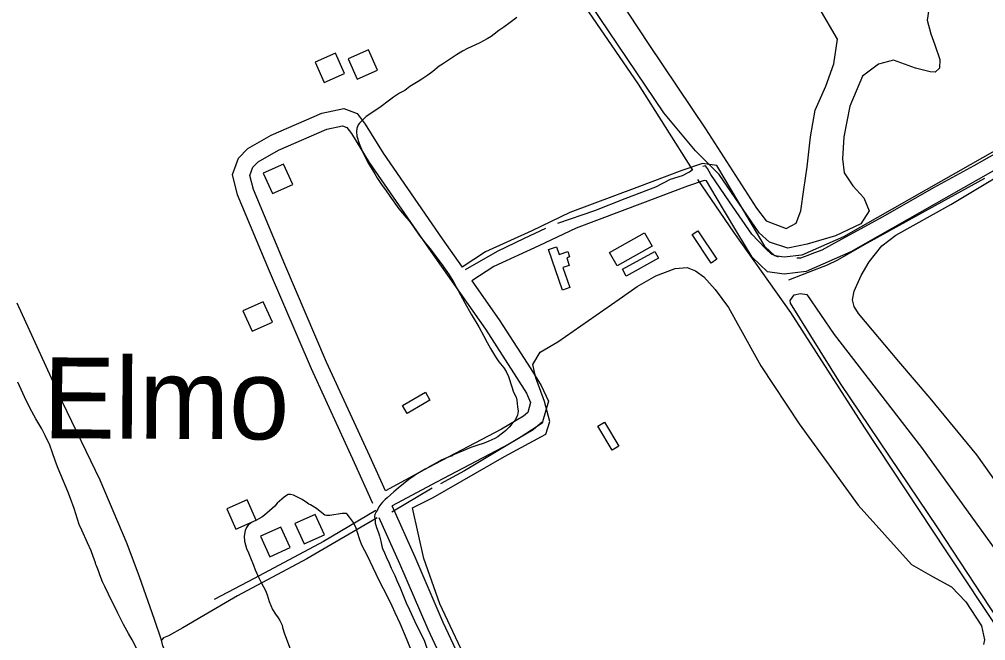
# Model space of a CAD drawing. Extents: x 3392644 to 3430565, y 576657 to 602123.
# Drawn here: x 3398161 to 3399896, y 589018 to 590133 of the extents above; entities that cross this region are included whole.
import ezdxf

# ---------------------------------------------------------------- set-up
doc = ezdxf.new("R2010")
doc.units = 0
for name, color, linetype in [('V-BLDG-OTLN', 7, 'Continuous'), ('V-ROAD-CNTR', 7, 'Continuous'), ('V-SITE-VEGE', 7, 'Continuous'), ('V-TOPO-GNAM-IDEN', 7, 'Continuous'), ('V-TOPO-SHOR', 7, 'Continuous')]:
    doc.layers.add(name, color=color, linetype=linetype)

msp = doc.modelspace()

# ---------------------------------------------------------------- linework, layer by layer
at = {"layer": 'V-BLDG-OTLN'}
for points in [[(3398804.1, 590042.1), (3398787.7, 590078.6), (3398751.2, 590062.2), (3398767.6, 590025.7)], [(3398744.7, 590036.3), (3398728.3, 590072.8), (3398691.8, 590056.4), (3398708.2, 590019.9)], [(3398651.8, 589836.9), (3398635.4, 589873.4), (3398598.9, 589857), (3398615.3, 589820.5)], [(3399296.8, 589726.1), (3399233.9, 589690.7), (3399220.4, 589714.7), (3399283.3, 589750.1)], [(3399402.7, 589695.8), (3399368.9, 589747.2), (3399379.2, 589754), (3399413, 589702.6)], [(3399136.2, 589647.5), (3399111, 589720.4), (3399125, 589725.2), (3399129.9, 589711), (3399145.5, 589716.4), (3399148.8, 589706.9), (3399143.5, 589705.1), (3399148.1, 589691.8), (3399136.6, 589687.9), (3399149, 589651.9)], [(3399308.6, 589704.6), (3399250.4, 589672.4), (3399243.6, 589684.7), (3399301.8, 589716.9)], [(3398615.2, 589590), (3398598.8, 589626.5), (3398562.3, 589610.2), (3398578.7, 589573.7)], [(3398848.9, 589440.2), (3398889.9, 589464.2), (3398898.1, 589450), (3398857.2, 589426.1)], [(3399211.3, 589410.4), (3399237.1, 589367.5), (3399225.1, 589360.3), (3399199.3, 589403.1)], [(3398586.3, 589234.8), (3398569.9, 589271.3), (3398533.4, 589254.9), (3398549.8, 589218.5)], [(3398708.7, 589208.2), (3398692.3, 589244.7), (3398655.8, 589228.4), (3398672.2, 589191.9)], [(3398647, 589185.5), (3398630.7, 589221.9), (3398594.2, 589205.6), (3398610.6, 589169.1)]]:
    msp.add_lwpolyline(points, close=True, dxfattribs=at)
at = {"layer": 'V-ROAD-CNTR'}
for points in [[(3400711.5, 590349.2), (3400649.5, 590311.2), (3400302.5, 590119), (3399788.6, 589827.2), (3399640.3, 589742.8), (3399565.5, 589710.1), (3399533.9, 589706.2), (3399517.4, 589708.6), (3399500, 589725.1), (3399476.5, 589764.4), (3399450.7, 589807.6), (3399427.9, 589845.8), (3399413, 589870.9), (3399387.4, 589874.5), (3399350.1, 589862), (3399269.3, 589831.7), (3399149, 589786.4), (3399080.9, 589753.9), (3398998.1, 589716.1), (3398955.9, 589688.4)], [(3400727.1, 590323.6), (3400664.6, 590285.3), (3400317.1, 590092.8), (3399803.4, 589801.1), (3399653.7, 589716), (3399573.5, 589680.9), (3399533.6, 589675.9), (3399503.7, 589680.3), (3399476.3, 589706.2), (3399450.8, 589749), (3399425, 589792.2), (3399402.2, 589830.4), (3399394.5, 589843.2), (3399390.2, 589843.8), (3399360.2, 589833.7), (3399279.8, 589803.6), (3399160.8, 589758.8), (3399093.6, 589726.8), (3399012.7, 589689.7), (3398973.2, 589663.8)], [(3398795.4, 589264.8), (3398762.8, 589337.3), (3398685.2, 589506), (3398610.1, 589681.6), (3398552.6, 589818.5), (3398543.4, 589854.7), (3398554.3, 589884.1), (3398571, 589901.6), (3398612.9, 589925.2), (3398704.1, 589965), (3398743.6, 589973), (3398767.6, 589964.1), (3398781.8, 589945.2), (3398814.3, 589893), (3398919.8, 589739.6), (3398955.9, 589688.4)], [(3398818.1, 589287.5), (3398790.1, 589349.7), (3398712.6, 589518.2), (3398637.7, 589693.3), (3398581.1, 589828.1), (3398574.8, 589853), (3398580.3, 589867.9), (3398589.6, 589877.7), (3398626.3, 589898.3), (3398713.2, 589936.3), (3398741.2, 589941.9), (3398748.9, 589939.1), (3398757, 589928.3), (3398789.2, 589876.5), (3398895.2, 589722.5), (3398997.6, 589577.1), (3399053.6, 589490.3), (3399071.1, 589462.2), (3399078.8, 589445.7), (3399073.6, 589427.8), (3399066, 589421.1), (3399026.5, 589397.9), (3398895.6, 589329.2), (3398818.1, 589287.5)], [(3398973.2, 589663.8), (3399022.5, 589593.9), (3399079, 589506.3), (3399097.5, 589476.5), (3399110.7, 589448.1), (3399099.9, 589410.9), (3399083.6, 589396.7), (3399041.1, 589371.7), (3398909.7, 589302.7), (3398830.4, 589260.1)], [(3399121.8, 588567.7), (3399100.4, 588614.9), (3399064.5, 588719.1), (3399033.2, 588806), (3398982, 588922.5), (3398922.1, 589050.7), (3398871.7, 589168.3), (3398830.4, 589260.1)], [(3398801.1, 589252.2), (3398706.9, 589196.6), (3398582.7, 589129.8), (3398510.7, 589092.2)], [(3399095.7, 588552.4), (3399072.5, 588603.8), (3399036.2, 588709.1), (3399005.4, 588794.9), (3398954.7, 588910.1), (3398894.7, 589038.4), (3398844.2, 589156.2), (3398807.2, 589238.6)]]:
    msp.add_lwpolyline(points, dxfattribs=at)
at = {"layer": 'V-SITE-VEGE'}
for points in [[(3399178.7, 590259.3), (3399291.1, 590088.2), (3399392.7, 589937), (3399484.2, 589794.6), (3399501.3, 589771.5), (3399537.4, 589757.7), (3399555.7, 589767.7), (3399563.8, 589789.7), (3399569, 589827.6), (3399575, 589868.5), (3399581.2, 589922.1), (3399589.7, 589970.2), (3399608.4, 590013.4), (3399623, 590053.5), (3399629.9, 590097.6), (3399596.6, 590154)], [(3399793.5, 590151.7), (3399790.6, 590132), (3399797, 590107), (3399804.6, 590087.2), (3399813, 590061), (3399812.4, 590045.3), (3399804.8, 590038.6), (3399796.1, 590038.8), (3399769.4, 590045.4), (3399730.1, 590060.1), (3399703.2, 590052.5), (3399674.5, 590031.5), (3399651.7, 589977.3), (3399640.8, 589922.2), (3399638.8, 589882.8), (3399641.6, 589857.5), (3399657.1, 589834.4), (3399676.6, 589812.8), (3399686.6, 589789.8), (3399671.3, 589766.3), (3399626, 589744.8), (3399575.3, 589729.6), (3399540.5, 589722.9), (3399507.5, 589733.6), (3399488.8, 589750.4), (3399417.4, 589854.6), (3399374.5, 589897), (3399317.7, 589965.6), (3399170.3, 590185.2)], [(3399046.8, 590131.2), (3399042.2, 590127.5), (3399030.8, 590119.2), (3399021.8, 590112.9), (3399013.6, 590106.6), (3399007.7, 590102.4), (3399000.9, 590098.5), (3398987.6, 590091.2), (3398978.5, 590086.8), (3398965.2, 590080.7), (3398956.5, 590076), (3398945.7, 590069.3), (3398938.6, 590064.9), (3398920.6, 590052.9), (3398914.7, 590049.2), (3398903.2, 590039.6), (3398894.5, 590033.1), (3398883.3, 590025.7), (3398877.2, 590021.7), (3398867.9, 590016.5), (3398861.8, 590012.5), (3398853, 590005.4), (3398850.6, 590004.5), (3398843.7, 590000.7), (3398832.7, 589993.5), (3398825.5, 589988.3), (3398808.3, 589974.8), (3398783.8, 589958.9), (3398779.6, 589954.7), (3398776.7, 589951.7), (3398771.6, 589947.2), (3398769.5, 589943.7), (3398766.9, 589937.5), (3398766.1, 589931.7), (3398766.7, 589923.6), (3398770.9, 589910.3), (3398776.7, 589897.2), (3398786.6, 589876.2), (3398799.3, 589855.9), (3398803.9, 589847.5), (3398812.2, 589835.1), (3398818.1, 589827), (3398826.1, 589815.7), (3398842.5, 589793.5), (3398855.3, 589777.8), (3398860.5, 589771.7), (3398868.3, 589761.1), (3398879, 589746), (3398889.5, 589732.3), (3398898, 589722), (3398911, 589704.9), (3398919.9, 589692.9), (3398932.6, 589674.6), (3398941.1, 589660.8), (3398952.8, 589638.9), (3398960.7, 589624.3), (3398972.1, 589604), (3398986.1, 589581.2), (3398995.1, 589564.5), (3399000.6, 589553.5), (3399006.5, 589542.9), (3399015.7, 589527.5), (3399022, 589518.9), (3399030.5, 589507.9), (3399034.9, 589501.2), (3399038.8, 589492.5), (3399040.8, 589487.2), (3399043.1, 589479.2), (3399044.9, 589473.6), (3399047.6, 589466.2), (3399049.4, 589461.8), (3399052.9, 589455.2), (3399054, 589450.1), (3399055.5, 589438), (3399056.2, 589429.9), (3399055.5, 589422.7), (3399051.6, 589415.3), (3399049.5, 589411.9), (3399043.6, 589405.6), (3399040.3, 589401.5), (3399034.2, 589395.5), (3399030.6, 589392.2), (3399023.5, 589387.2), (3399019.9, 589384.4), (3399014.4, 589381.3), (3399004, 589376.2), (3398995.3, 589372.9), (3398982.4, 589368.4), (3398975.2, 589366.2), (3398968.6, 589363.7), (3398957.8, 589359.1), (3398948.5, 589355.5), (3398935.4, 589350), (3398939, 589350.9), (3398929.3, 589347.1), (3398918.5, 589342.5), (3398902.6, 589333.5), (3398895.6, 589329.3), (3398889.7, 589326.3), (3398875.4, 589317.9), (3398869.7, 589314.2)], [(3399053.8, 590136.4), (3399046.8, 590131.2)], [(3399948.2, 589254.9), (3399879.9, 589351.6), (3399795.9, 589453.3), (3399739.4, 589519.1), (3399667, 589605.2), (3399659.3, 589617.9), (3399656.7, 589629.8), (3399659.6, 589645.2), (3399672.2, 589673.8), (3399686.3, 589698.1), (3399709.1, 589726.7), (3399734.2, 589745.7), (3399833.2, 589801), (3399978.7, 589888)], [(3399014.5, 588874.6), (3398916, 589084.2), (3398887, 589165.8), (3398866.8, 589256.9), (3398904.1, 589275.4), (3399032.1, 589348.8), (3399106, 589389), (3399113.3, 589411.8), (3399103.5, 589447.4), (3399088.2, 589490.2), (3399083, 589514), (3399095.9, 589535.9), (3399127.7, 589554.5), (3399237.5, 589631.3), (3399270.2, 589653.8), (3399303.6, 589673.1), (3399338.4, 589686.1), (3399359.8, 589688.2), (3399374.7, 589681.8), (3399389.6, 589671.3), (3399409.8, 589648.2), (3399433.9, 589616.3), (3399452.5, 589582.9), (3399491.8, 589511.4), (3399560.9, 589407.2), (3399666.5, 589261.5), (3399762.3, 589155.3), (3399799.9, 589133.6), (3399834.4, 589115), (3399860.1, 589087.8), (3399888, 589044.9), (3399893.3, 589019.6), (3399891.6, 589011.7)], [(3399931.8, 589006.1), (3399935.9, 589020.2), (3399929.8, 589037.7), (3399809.6, 589220.7), (3399635.1, 589480.1), (3399545.3, 589624.1), (3399544.6, 589628.8), (3399551.8, 589639), (3399562.9, 589641.2), (3399574.7, 589639.5), (3399623.6, 589567.9), (3399780.6, 589364.7), (3400002.6, 589057.3), (3400213, 588764.3)], [(3398372.9, 589001.6), (3398363.7, 589019.7), (3398356.9, 589031.4), (3398347.9, 589047.4), (3398342.8, 589058), (3398337.8, 589067.7), (3398332.9, 589078.1), (3398325.6, 589092.7), (3398321.2, 589102), (3398314.4, 589115.3), (3398310.4, 589124), (3398305.3, 589136.3), (3398302.9, 589143.5), (3398299.3, 589152.6), (3398298.4, 589155.1), (3398297.5, 589158.1), (3398293.7, 589169.5), (3398290, 589179.5), (3398283.3, 589193.9), (3398273.4, 589216.7), (3398268.7, 589226.7), (3398259.5, 589255.5), (3398253.1, 589273.5), (3398248.4, 589286), (3398235.6, 589315.7), (3398230.9, 589327.3), (3398226.2, 589339.6), (3398220.2, 589357.4), (3398215.8, 589369.1), (3398207.6, 589386.6), (3398201.4, 589398.7), (3398190.9, 589416.6), (3398183.7, 589429.7), (3398173.6, 589449.2), (3398167.2, 589462.3), (3398158.1, 589482.4)], [(3398869.7, 589314.2), (3398860, 589307.5), (3398840.8, 589292), (3398833.5, 589285.7), (3398821.5, 589274.7), (3398817.9, 589271.6), (3398812.9, 589266.9), (3398809.9, 589263.6), (3398806.6, 589258.4), (3398804.3, 589254.1), (3398801.6, 589249.6), (3398799.2, 589244.5), (3398798.6, 589241), (3398798.9, 589237.2), (3398799.5, 589234.5), (3398800, 589229.3), (3398801, 589225.7), (3398802.1, 589221.3), (3398805.4, 589213.4), (3398807.4, 589206.7), (3398810.1, 589196.9), (3398811.8, 589187.8), (3398813.1, 589183.9), (3398816.7, 589175.9), (3398819.3, 589169.1), (3398824.6, 589157.5), (3398828.4, 589148.6), (3398834.8, 589135.1), (3398838.5, 589126.4), (3398844.7, 589113.3), (3398855.6, 589086.4), (3398861.1, 589073.7), (3398870.2, 589054), (3398877.2, 589040), (3398887.6, 589019.1), (3398892.5, 589005.1)], [(3398863.3, 589004.6), (3398857.1, 589019), (3398844.9, 589049.1), (3398835.8, 589068.1), (3398830.5, 589080.2), (3398822.4, 589096.7), (3398807.2, 589126.5), (3398785.4, 589172), (3398776, 589189.5), (3398771.5, 589201.4), (3398765.7, 589220.5), (3398760.6, 589230.4), (3398753.4, 589239.7), (3398749.5, 589245.4), (3398747.6, 589246.4), (3398740.7, 589246.3), (3398718.4, 589242.8), (3398712.4, 589242.9), (3398709.7, 589243.7), (3398700.8, 589250.2), (3398694.6, 589255.8), (3398683.8, 589262), (3398681, 589263.5), (3398678.4, 589265.4), (3398668.9, 589271.8), (3398653, 589279.2), (3398647.7, 589280.6), (3398643.4, 589280.4), (3398636.9, 589276.6), (3398632.5, 589272.3), (3398624.1, 589264.9), (3398619.7, 589259.7), (3398605.6, 589247.2), (3398598.2, 589241.3)], [(3398598.2, 589241.3), (3398596.6, 589239.8), (3398590.8, 589236.7), (3398586.8, 589234.9), (3398580.3, 589231.8), (3398577.9, 589230.5), (3398574.6, 589228.3), (3398572.2, 589226.6), (3398568.9, 589221.6), (3398566.4, 589216.1), (3398564.7, 589205.8), (3398565.5, 589196.9), (3398569.1, 589183.9), (3398572.4, 589175.7), (3398576.2, 589167), (3398581.5, 589154.1), (3398584.6, 589145.6), (3398591.2, 589131.2), (3398595.9, 589121.7), (3398602.7, 589108.6), (3398606.2, 589100.5), (3398609.6, 589088.6), (3398612.3, 589081.2), (3398615.4, 589074.5), (3398620.6, 589066.2), (3398625.8, 589059.5), (3398628.9, 589054.4), (3398631.8, 589048.7), (3398632.6, 589046.4), (3398633.4, 589042.3), (3398637.2, 589030.5), (3398647.2, 589003.8)]]:
    msp.add_lwpolyline(points, dxfattribs=at)
at = {"layer": 'V-TOPO-SHOR'}
for p, q in [((3399370, 589863.2), (3399369.6, 589863.9)), ((3398902.3, 589291.8), (3398829.9, 589248.9))]:
    msp.add_line(p, q, dxfattribs=at)
for points in [[(3399369.6, 589863.9), (3399272.3, 590016.8), (3399156.8, 590185.7), (3399045, 590350.3), (3398963.8, 590473.2)], [(3400120.6, 590009.9), (3400038.1, 589964.6), (3399952.8, 589914.8), (3399874.6, 589870.2), (3399802.1, 589830.9), (3399710.7, 589778.7), (3399630.8, 589734.9), (3399601.3, 589719.1), (3399583.6, 589712.5), (3399576.1, 589709.5), (3399562.9, 589704.7), (3399556.6, 589704.7)], [(3399523.7, 589706.5), (3399510.9, 589711.9), (3399500.2, 589721.9), (3399475.9, 589747.5), (3399436, 589805.5), (3399402.5, 589855), (3399396.1, 589865.8), (3399392.4, 589870.1), (3399387.6, 589869.3)], [(3399127.8, 589767.4), (3399193.9, 589790.5), (3399248.6, 589812), (3399303.3, 589832.6), (3399329.8, 589846.3), (3399351.6, 589853), (3399363.8, 589859.4), (3399369.6, 589863.9)], [(3399923.4, 589013.8), (3399924.8, 589029.7), (3399824.7, 589179.5), (3399678.8, 589400.1), (3399545.6, 589607.3), (3399443.6, 589751.5), (3399378.9, 589845.6)], [(3399893.3, 589847.4), (3399775.2, 589782.2), (3399677.2, 589728.5), (3399629.5, 589701.3), (3399610.8, 589692), (3399576.9, 589679.2), (3399541.4, 589665)], [(3398962.1, 589684.1), (3399019.4, 589717.1), (3399067.9, 589740.8), (3399106, 589758.5)], [(3398714.5, 588314.1), (3398705, 588341.7), (3398685.2, 588397.5), (3398645.1, 588481.9), (3398601.2, 588587.4), (3398559.4, 588685.6), (3398518.9, 588769.5), (3398471.1, 588885.1), (3398434, 588976.3), (3398418.5, 589009.1), (3398416, 589019.2), (3398403.4, 589056.6), (3398376.6, 589132.7), (3398354.9, 589192), (3398306.2, 589306.4), (3398238.4, 589446.6), (3398157.2, 589624.1)], [(3399100.2, 589409.8), (3399099.9, 589409), (3399088.8, 589401.2), (3399061.8, 589383.9), (3398959.9, 589323.4), (3398917, 589300)], [(3398803.6, 589238.7), (3398676.9, 589165.4), (3398552.8, 589099.1)], [(3398552.8, 589099.1), (3398492, 589063.7), (3398454.5, 589041.2), (3398428.7, 589027.2), (3398419.7, 589023.3), (3398416, 589019.2)]]:
    msp.add_lwpolyline(points, dxfattribs=at)

# ---------------------------------------------------------------- texts
at = {"layer": 'V-TOPO-GNAM-IDEN'}
msp.add_text('St. Elmo', height=145, rotation=359.6858, dxfattribs=at).set_placement((3397912.5, 589383.3))

doc.saveas('drawing.dxf')
